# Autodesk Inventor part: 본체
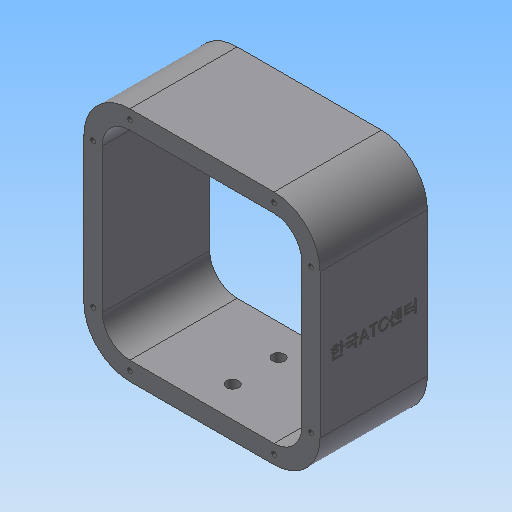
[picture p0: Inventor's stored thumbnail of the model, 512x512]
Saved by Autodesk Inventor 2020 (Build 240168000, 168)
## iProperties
Created: 2016-12
Part Number: 본체
Material: 일반
Document SubType Name: Modeling
Designer: mduedu
Density: 1 g/cm^3
Appearance: 기본값
Author: mduedu
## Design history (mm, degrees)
sketch "스케치1"
  geometry: L1 (-54, 50)-(-54, -44); L2 (-24, 80)-(70, 80); L3 (100, 50)-(100, -44); L4 (70, -74)-(-24, -74); A1 r 30 centre (-24, -44) between (-54, -44) and (-24, -74); A2 r 30 centre (70, 50) between (100, 50) and (70, 80); A3 r 30 centre (70, -44) between (70, -74) and (100, -44); A4 r 30 centre (-24, 50) between (-24, 80) and (-54, 50); 1 further point
  constraints: 8 end point, 8 point on circle, 8 tangent, 4 centre point, 3 equal radius, 2 perpendicular, 1 horizontal, 1 vertical
  dimensions: "d83" = 30 radius of A2; "d84" = 100 distance from line of L3 point (0, 0); "d85" = 154 distance between parallel lines of L4 L2; "d87" = 80 distance from line of point (0, 0) L2
extrude "돌출1" new body sketch "스케치1" stored distance "d3" = 70; taper "d4" = 0 deg
feature "쉘1" dims "d5" = 12
sketch "스케치10"
  geometry: 2 further points
  constraints: 1 coincident, 1 other
feature "엠보싱1" sketch "스케치10" dims "d61" = 0.5, "d62" = 0
sketch "스케치11"
  geometry: L1 (-42, -44)-(-42, 50) reference; L2 (-24, 68)-(70, 68) reference; L3 (88, 50)-(88, -44) reference; L4 (70, -62)-(-24, -62) reference; L5 (-24, -74)-(70, -74) reference; L6 (100, -44)-(100, 50) reference; L7 (70, 80)-(-24, 80) reference; L8 (-54, 50)-(-54, -44) reference; L9 (-24, 74)-(70, 74); L10 (94, 50)-(94, -44); L11 (70, -68)-(-24, -68); L12 (-48, -44)-(-48, 50); A1 r 18 centre (-24, -44) between (-42, -44) and (-24, -62) reference; A2 r 18 centre (-24, 50) between (-24, 68) and (-42, 50) reference; A3 r 18 centre (70, 50) between (88, 50) and (70, 68) reference; A4 r 18 centre (70, -44) between (70, -62) and (88, -44) reference; A5 r 30 centre (-24, -44) between (-54, -44) and (-24, -74) reference; A6 r 30 centre (70, -44) between (70, -74) and (100, -44) reference; A7 r 30 centre (70, 50) between (100, 50) and (70, 80) reference; A8 r 30 centre (-24, 50) between (-24, 80) and (-54, 50) reference; A9 r 24 centre (70, 50) between (94, 50) and (70, 74); A10 r 24 centre (70, -44) between (70, -68) and (94, -44); A11 r 24 centre (-24, -44) between (-48, -44) and (-24, -68); A12 r 24 centre (-24, 50) between (-24, 74) and (-48, 50); 8 further points
  constraints: 8 coincident, 8 end point, 8 point on circle, 4 centre point, 7 other
  dimensions: "d90" = 6 distance between parallel lines of L9 L7
hole "구멍3" sketch "스케치11" at (-24, 74), (-48, 50), (-48, -44), (-24, -68), (70, -68), (94, -44), (94, 50), (70, 74) diameter "d63" = 3.242; stored, may be unused: countersink angle "d67" = 90 deg, drill point angle "d69" = 120 deg; dims "d64" = 8.6, "d65" = 4, "d66" = 2, "d68" = 10.6
sketch "스케치12"
  geometry: L1 (24, -62)-(-70, -62) reference; L2 (-88, -44)-(-88, 50) reference; L3 (-70, 68)-(24, 68) reference; L4 (42, 50)-(42, -44) reference; L5 (54, -44)-(54, 50) reference; L6 (24, 80)-(-70, 80) reference; L7 (-100, 50)-(-100, -44) reference; L8 (-70, -74)-(24, -74) reference; L9 (-70, 74)-(24, 74); L10 (48, 50)-(48, -44); L11 (24, -68)-(-70, -68); L12 (-94, -44)-(-94, 50); A1 r 18 centre (24, -44) between (24, -62) and (42, -44) reference; A2 r 18 centre (-70, -44) between (-88, -44) and (-70, -62) reference; A3 r 18 centre (-70, 50) between (-70, 68) and (-88, 50) reference; A4 r 18 centre (24, 50) between (42, 50) and (24, 68) reference; A5 r 30 centre (24, -44) between (24, -74) and (54, -44) reference; A6 r 30 centre (24, 50) between (54, 50) and (24, 80) reference; A7 r 30 centre (-70, 50) between (-70, 80) and (-100, 50) reference; A8 r 30 centre (-70, -44) between (-100, -44) and (-70, -74) reference; A9 r 24 centre (24, 50) between (48, 50) and (24, 74); A10 r 24 centre (24, -44) between (24, -68) and (48, -44); A11 r 24 centre (-70, -44) between (-94, -44) and (-70, -68); A12 r 24 centre (-70, 50) between (-70, 74) and (-94, 50); 8 further points
  constraints: 8 coincident, 8 end point, 8 point on circle, 4 centre point, 7 other
  dimensions: "d91" = 6 distance between parallel lines of L9 L6
hole "구멍5" sketch "스케치12" at (-70, 74), (-94, 50), (-94, -44), (-70, -68), (24, -68), (48, -44), (48, 50), (24, 74) diameter "d70" = 3.242; stored, may be unused: countersink angle "d74" = 90 deg, drill point angle "d76" = 120 deg; dims "d71" = 8.6, "d72" = 4, "d73" = 2, "d75" = 10.6
sketch "스케치15"
  geometry: L1 (154.8, -35)-(-60.8, -35) reference; L2 (94, 0)-(0, 0) reference; L3 (0, -70)-(94, -70) reference; L4 (47, 0)-(47, -70); C1 r 4 at (47, -20); C2 r 4 at (47, -50); 1 further point
  constraints: 2 centre point, 2 end point, 2 midpoint, 1 point on line, 1 symmetric about line, 1 other
  dimensions: "d92" = 8 diameter of C1; "d93" = 15 distance from line of C1.centre L1
extrude "돌출6" cut sketch "스케치15" extent not by distance; stored distance "d94" = 10; taper "d95" = 0 deg
node "솔리드1"
node "투영된 루프3"
node "투영된 루프4"
